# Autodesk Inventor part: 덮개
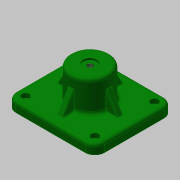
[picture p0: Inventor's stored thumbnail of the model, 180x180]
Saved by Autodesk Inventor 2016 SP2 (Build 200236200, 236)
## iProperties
Created: 2017-08
Part Number: 덮개
Material: 알루미늄 6061
Document SubType Name: Modeling
Designer: mduedu
Density: 1 g/cm^3
Appearance: 진녹색
Author: mduedu
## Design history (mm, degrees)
sketch "스케치1"
  geometry: L1 (46, -41)-(-46, -41); L2 (-46, -41)-(-46, 41); L3 (-46, 41)-(46, 41); L4 (46, 41)-(46, -41); 1 further point
  constraints: 8 end point, 2 parallel, 1 horizontal, 1 perpendicular
  dimensions: "d0" = 92 distance of L2.end L3.end; "d2" = 82 distance of L1.end L2.end; "d3" = 41 distance from line of L3 point (0, 0) (= 0.5 x d2); "d4" = 46 distance from line of point (0, 0) L4 (= 0.5 x d0)
extrude "돌출1" new body sketch "스케치1" distance "d5" = 10; taper "d6" = 0 deg
sketch "스케치2"
  geometry: C1 r 20 at (0, 0); 1 further point
  constraints: 1 centre point, 1 coincident
  dimensions: "d55" = 40 diameter of C1
extrude "돌출2" join sketch "스케치2" distance "d9" = 32; taper "d10" = 0 deg
sketch "스케치3"
  geometry: L1 (-26, -26)-(26, -26); L2 (26, -26)-(26, 26); L3 (26, 26)-(-26, 26); L4 (-26, 26)-(-26, -26); L5 (-26, -26)-(26, 26); L6 (26, -26)-(-26, 26); 1 further point
  constraints: 12 end point, 2 midpoint, 2 parallel, 2 perpendicular, 1 horizontal
  dimensions: "d11" = 52 distance of L3.end L2.end
extrude "돌출3" join sketch "스케치3" distance "d12" = 6; taper "d13" = 0 deg
sketch "스케치4"
  geometry: L1 (-17, -17)-(17, -17); L2 (17, -17)-(17, 17); L3 (17, 17)-(-17, 17); L4 (-17, 17)-(-17, -17); L5 (-17, -17)-(17, 17); L6 (17, -17)-(-17, 17); 1 further point
  constraints: 12 end point, 2 midpoint, 2 parallel, 2 perpendicular, 1 horizontal
  dimensions: "d14" = 34 distance of L2.end L3.end
extrude "돌출4" cut sketch "스케치4" distance "d16" = 5; taper "d17" = 0 deg
sketch "스케치5"
  geometry: C1 r 9 at (0, 0); 1 further point
  constraints: 1 centre point, 1 coincident
  dimensions: "d18" = 18 diameter of C1
extrude "돌출5" cut sketch "스케치5" distance "d19" = 34; taper "d20" = 0 deg
sketch "스케치6"
  geometry: 2 further points
  constraints: 1 coincident
hole "구멍1" sketch "스케치6" at (0, 0) diameter "d21" = 5.917; stored, may be unused: countersink angle "d25" = 90 deg, drill point angle "d27" = 118 deg; dims "d22" = 6, "d23" = 14, "d24" = 2, "d26" = 8
fillet "모깎기1" dims "d36" = 10
fillet "모깎기3" dims "d38" = 3
fillet "모깎기4" dims "d39" = 3
fillet "모깎기5" dims "d40" = 3
chamfer "모따기1" distance "d41" = 1; stored, may be unused: second distance "d42" = 2, angle "d43" = 45 deg
fillet "모깎기6" dims "d44" = 3
fillet "모깎기7" dims "d45" = 3
fillet "모깎기8" dims "d46" = 3
sketch "스케치8"
  geometry: A1 r 10 centre (-36, -31) between (-46, -31) and (-36, -41) reference; A2 r 10 centre (-36, 31) between (-36, 41) and (-46, 31) reference; A3 r 10 centre (36, 31) between (46, 31) and (36, 41) reference; A4 r 10 centre (36, -31) between (36, -41) and (46, -31) reference; 5 further points
  constraints: 4 coincident
sketch "스케치9"
  geometry: 4 further points
  constraints: 4 other
hole "구멍3" sketch "스케치9" at (-36, -31), (-36, 31), (36, 31), (36, -31) diameter "d48" = 4.5; stored, may be unused: countersink angle "d52" = 90 deg, drill point angle "d54" = 0 deg; dims "d49" = 6, "d50" = 8, "d51" = 4.6, "d53" = 8
sketch "스케치10"
  geometry: L1 (-7, 40)-(-2.958, 40) reference; L2 (-2.958, 40)-(-2.958, 33) reference; L3 (-2.958, 33)-(-6, 33) reference; L4 (-9, 30)-(-9, -1) reference; L5 (-9, -1)-(-14, -1) reference; L6 (-17, -4)-(-17, -6) reference; L7 (-17, -6)-(-25, -6) reference; L8 (-25, -6)-(-26, -5) reference; L9 (-26, -5)-(-26, 0) reference; L10 (-26, 0)-(-46, 0) reference; L11 (-46, 0)-(-46, 7) reference; L12 (-43, 10)-(-23, 10) reference; L13 (-20, 13)-(-20, 39) reference; L14 (-17, 42)-(-7, 42) reference; L15 (-7, 42)-(-7, 40) reference; L16 (2.958, 40)-(7, 40) reference; L17 (7, 40)-(7, 42) reference; L18 (7, 42)-(17, 42) reference; L19 (20, 39)-(20, 13) reference; L20 (23, 10)-(43, 10) reference; L21 (46, 7)-(46, 0) reference; L22 (46, 0)-(26, 0) reference; L23 (26, 0)-(26, -5) reference; L24 (26, -5)-(25, -6) reference; L25 (25, -6)-(17, -6) reference; L26 (17, -6)-(17, -4) reference; L27 (14, -1)-(9, -1) reference; L28 (9, -1)-(9, 30) reference; L29 (6, 33)-(2.958, 33) reference; L30 (2.958, 33)-(2.958, 40) reference; L31 (31.547, 10)-(20, 30); A1 r 3 centre (-6, 30) between (-6, 33) and (-9, 30) reference; A2 r 3 centre (-14, -4) between (-14, -1) and (-17, -4) reference; A3 r 3 centre (-43, 7) between (-43, 10) and (-46, 7) reference; A4 r 3 centre (-23, 13) between (-23, 10) and (-20, 13) reference; A5 r 3 centre (-17, 39) between (-17, 42) and (-20, 39) reference; A6 r 3 centre (17, 39) between (20, 39) and (17, 42) reference; A7 r 3 centre (23, 13) between (20, 13) and (23, 10) reference; A8 r 3 centre (43, 7) between (46, 7) and (43, 10) reference; A9 r 3 centre (14, -4) between (17, -4) and (14, -1) reference; A10 r 3 centre (6, 30) between (9, 30) and (6, 33) reference; 1 further point
  constraints: 2 end point, 2 point on line
  dimensions: "d56" = 20 distance from line of L31.end L20; "d57" = 120 deg angle of L31 L20
feature "리브1" sketch "스케치10" dims "d58" = 1, "d59" = 6, "d60" = 0, "d61" = 0, "d62" = 1, "d63" = 1
fillet "모깎기9" dims "d64" = 1
fillet "모깎기10" dims "d65" = 1
node "솔리드1"
pattern_circular "원형 패턴1" dims "d67" = 360 deg
node "절단 모서리 투영1"
